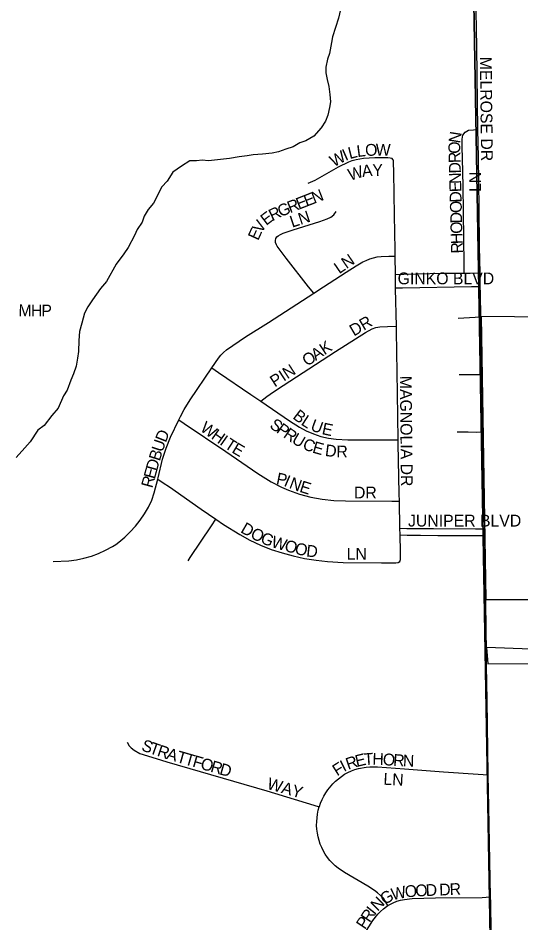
# Model space of a CAD drawing. Extents: x 1985906 to 2360102, y 891258 to 1222054.
# Drawn here: x 2128183 to 2130312, y 1037407 to 1041237 of the extents above; entities that cross this region are included whole.
import ezdxf

# ---------------------------------------------------------------- set-up
doc = ezdxf.new("R2010")
doc.units = 0
for name, color, linetype in [('GM_X_City_Street', 7, 'Continuous'), ('GM_X_City_Street_Text', 7, 'Continuous'), ('GM_X_Corporation', 7, 'Continuous'), ('GM_X_Minor_River', 7, 'Continuous'), ('GM_X_Section', 7, 'Continuous'), ('GM_X_Township_Road', 7, 'Continuous')]:
    doc.layers.add(name, color=color, linetype=linetype)

msp = doc.modelspace()

# ---------------------------------------------------------------- linework, layer by layer
at = {"layer": 'GM_X_City_Street'}
for points in [[(2130129.7, 1040765.1), (2130127.6, 1040879.5), (2130124.6, 1041114.9), (2130121.4, 1041343.2), (2130120.6, 1041445.2), (2130120.4, 1041459.6)], [(2130071.5, 1040157.7), (2130071.1, 1040195.2), (2130066.9, 1040526.3), (2130063.7, 1040643), (2130062.7, 1040692.7), (2130062.9, 1040725.3), (2130065.9, 1040741.2), (2130075, 1040754.4), (2130089.3, 1040762.6), (2130110.7, 1040763.9), (2130129.7, 1040765.1)], [(2130138.6, 1040158.3), (2130136.8, 1040269), (2130135, 1040434.1), (2130131.9, 1040648.5), (2130129.7, 1040765.1)], [(2129411.6, 1040538.5), (2129440.7, 1040550.6), (2129539.3, 1040607.9), (2129582.8, 1040629.2), (2129597.9, 1040634.8), (2129613.5, 1040639.1), (2129629.3, 1040642.1), (2129645.4, 1040644), (2129693.8, 1040647.1), (2129732.9, 1040647.1), (2129748.2, 1040646.5), (2129757.9, 1040645.9), (2129765.2, 1040643.6)], [(2129779.9, 1040229.5), (2129779.7, 1040255.8), (2129776.3, 1040403.3), (2129773.8, 1040583.6), (2129772, 1040627.3), (2129771.6, 1040633.2), (2129770.2, 1040637.7), (2129765.2, 1040643.6)], [(2129434.5, 1040072.4), (2129412.8, 1040100.3), (2129318.5, 1040221.3), (2129279.8, 1040271.1), (2129276.4, 1040277.9), (2129272.9, 1040287), (2129272, 1040296.3), (2129274.1, 1040304.8), (2129278.2, 1040311.2), (2129283.6, 1040316.1), (2129293.5, 1040321.8), (2129304.8, 1040327), (2129347.3, 1040341.4), (2129459.8, 1040376.4), (2129491.2, 1040387.8), (2129506.3, 1040394.9), (2129519.6, 1040405), (2129529.5, 1040418.5)], [(2129434.5, 1040072.4), (2129476.4, 1040099.3), (2129572.5, 1040161.3), (2129613.5, 1040188.5), (2129641.7, 1040204.9), (2129656.5, 1040211.8), (2129671.7, 1040217.8), (2129687.2, 1040222.6), (2129703.2, 1040226.2), (2129719.4, 1040228), (2129752, 1040228.8), (2129779.9, 1040229.5)], [(2129780.6, 1040152.1), (2129779.9, 1040229.5)], [(2129780.6, 1040152.1), (2129815.4, 1040152.9), (2129981.3, 1040156.8), (2130071.5, 1040157.7)], [(2129780.8, 1040095.5), (2129780.8, 1040124.6), (2129780.6, 1040152.1)], [(2130071.5, 1040157.7), (2130097.4, 1040157.9), (2130138.6, 1040158.3)], [(2130139.5, 1040101.3), (2130138.6, 1040158.3)], [(2129780.8, 1040095.5), (2129811, 1040096), (2130102.2, 1040100.7), (2130139.5, 1040101.3)], [(2129784.7, 1039932.6), (2129780.8, 1040091.8), (2129780.8, 1040095.5)], [(2130141.8, 1039972.1), (2130140, 1040071.2), (2130139.5, 1040101.3)], [(2129003.4, 1039756.8), (2129030.9, 1039797.4), (2129041, 1039810.3), (2129052.2, 1039822), (2129064.8, 1039832.3), (2129145.7, 1039887.7), (2129242.6, 1039948.9), (2129434.5, 1040072.4)], [(2130046.2, 1039967), (2130141.8, 1039972.1)], [(2129210.5, 1039615.5), (2129236.4, 1039635.2), (2129249.5, 1039645.2), (2129276.8, 1039664), (2129527.2, 1039826), (2129653.1, 1039906.5), (2129682.2, 1039921.8), (2129697.5, 1039927.5), (2129713.7, 1039930.8), (2129746.8, 1039931.6), (2129784.7, 1039932.6)], [(2129792.3, 1039452.3), (2129789.2, 1039649.4), (2129785.1, 1039911.5), (2129784.7, 1039932.6)], [(2128863.2, 1039537), (2128870.2, 1039551.3), (2128885.4, 1039580.2), (2128911.3, 1039621.8), (2129003.4, 1039756.8)], [(2129003.4, 1039756.8), (2129032.1, 1039736.7), (2129168.8, 1039644), (2129210.5, 1039615.5)], [(2130050.2, 1039728), (2130110.9, 1039728.7), (2130146.4, 1039729.1)], [(2129210.5, 1039615.5), (2129332.3, 1039532.2), (2129374, 1039505.6), (2129403, 1039489.7), (2129433.3, 1039476.9), (2129464.7, 1039466.7), (2129496.9, 1039459), (2129529.5, 1039454.5), (2129579, 1039452.3), (2129711.2, 1039451.9), (2129760.7, 1039452.1), (2129792.3, 1039452.3)], [(2128774.4, 1039285.4), (2128775.9, 1039291.1), (2128795, 1039370.7), (2128809.3, 1039417.5), (2128827.6, 1039462.9), (2128863.2, 1039537)], [(2128863.2, 1039537), (2128885.9, 1039521.7), (2129062.6, 1039402.1), (2129198.5, 1039309.8), (2129254.3, 1039275), (2129297.9, 1039252.1), (2129328, 1039238.9), (2129374.4, 1039222.4), (2129422.1, 1039209.6), (2129470.6, 1039200.6), (2129519.6, 1039195.5), (2129568.9, 1039193.3), (2129765.5, 1039192.8), (2129796.9, 1039192.8)], [(2130041.3, 1039486), (2130087.8, 1039485.9), (2130122.6, 1039485.1), (2130150.8, 1039485.9)], [(2129796.9, 1039192.8), (2129796.2, 1039223.3), (2129792.5, 1039436.4), (2129792.3, 1039452.3)], [(2128331.9, 1038937.6), (2128397.2, 1038940.6), (2128429.7, 1038944.2), (2128461.8, 1038950.6), (2128493.2, 1038959.4), (2128524, 1038970.5), (2128553.6, 1038984.4), (2128582.2, 1039000.3), (2128596.1, 1039009), (2128609.4, 1039018.5), (2128634.3, 1039039.6), (2128657.8, 1039062.3), (2128679.8, 1039086.3), (2128700.2, 1039111.8), (2128718.6, 1039138.9), (2128734.7, 1039167.3), (2128748.5, 1039197), (2128759.3, 1039227.8), (2128774.4, 1039285.4)], [(2128774.4, 1039285.4), (2128796.6, 1039270.7), (2128823.9, 1039252.8), (2128957.8, 1039159.2), (2129020.3, 1039116.1)], [(2129799.6, 1039077.5), (2129796.9, 1039192.8)], [(2128902.4, 1038939.9), (2128911, 1038953.6), (2129001.6, 1039088.3), (2129020.3, 1039116.1)], [(2129020.3, 1039116.1), (2129052, 1039094.3), (2129121.3, 1039051.1), (2129164.3, 1039027.4), (2129208.7, 1039006.7), (2129254.3, 1038988.6), (2129300.8, 1038973.2), (2129348.1, 1038960.5), (2129396.1, 1038950.3), (2129444.6, 1038942.5), (2129493.3, 1038937), (2129558.5, 1038932.9), (2129721.6, 1038931.5), (2129781.5, 1038932.1), (2129791.8, 1038933.3), (2129798.6, 1038937)], [(2129799.6, 1039077.5), (2129828.8, 1039077.4), (2129941.6, 1039077.3), (2130118.8, 1039075.4), (2130158.2, 1039075)], [(2129800.3, 1039049.4), (2129799.6, 1039077.5)], [(2129798.6, 1038937), (2129801.8, 1038945), (2129802.2, 1038954.7), (2129801.9, 1038977.4), (2129800.3, 1039049.4)], [(2129800.3, 1039049.4), (2129830.5, 1039049.1), (2129887, 1039048.4), (2129959.5, 1039047.5), (2130061.7, 1039047.5), (2130124.6, 1039047.5), (2130158.7, 1039047.6)], [(2130165.8, 1038556.3), (2130163.9, 1038652.3), (2130162.4, 1038766.8)], [(2130173.3, 1038034.8), (2130168.5, 1038350.2), (2130166.1, 1038496.9)], [(2128644.8, 1038171.9), (2128652.6, 1038157.5), (2128662, 1038147.8), (2128674.8, 1038138.4), (2128699.1, 1038123.8), (2128767.2, 1038103.3), (2128812.8, 1038089.7), (2129236, 1037966.7), (2129435.2, 1037906.1), (2129458.2, 1037899.1)], [(2129458.2, 1037899.1), (2129458.3, 1037899.5), (2129463.7, 1037914.7), (2129470.1, 1037929.5), (2129477.5, 1037943.8), (2129485.8, 1037957.7), (2129494.9, 1037971), (2129515.5, 1037995.8), (2129526.9, 1038007.1), (2129539.2, 1038017.5), (2129565.3, 1038036.4), (2129579.3, 1038044.2), (2129594, 1038050.7), (2129609.1, 1038056.2), (2129624.6, 1038060.7), (2129656.3, 1038066.5), (2129672.4, 1038068), (2129704.8, 1038068.3), (2129819.3, 1038060), (2129983.4, 1038047.2), (2130131.2, 1038037.6), (2130173.3, 1038034.8)], [(2130183.1, 1037517.2), (2130175.4, 1037896.8), (2130173.3, 1038034.8)], [(2129748.3, 1037480.5), (2129743.6, 1037488.8), (2129735.8, 1037502.5), (2129729.2, 1037511.5), (2129717.6, 1037523.6), (2129704.7, 1037534.5), (2129691.3, 1037544.4), (2129663.6, 1037562.5), (2129564.1, 1037620.5), (2129537.4, 1037638.8), (2129524.9, 1037649), (2129513.3, 1037660), (2129502.4, 1037671.7), (2129492.5, 1037684.4), (2129483.6, 1037697.8), (2129475.6, 1037711.8), (2129468.5, 1037726.3), (2129462.4, 1037741.3), (2129457.2, 1037756.6), (2129453, 1037772.2), (2129449.9, 1037788), (2129447.8, 1037803.9), (2129446.9, 1037820), (2129447.1, 1037836.1), (2129450.7, 1037868.2), (2129454, 1037884), (2129458.2, 1037899.1)], [(2129748.3, 1037480.5), (2129756.4, 1037485.6), (2129771.2, 1037492.9), (2129786.5, 1037498.8), (2129802.3, 1037503.5), (2129818.4, 1037506.9), (2129851.2, 1037510.4), (2129950, 1037513.2), (2130147.7, 1037515.1), (2130164.1, 1037516.1), (2130183.1, 1037517.2)], [(2130188.5, 1037189.7), (2130186, 1037367.3), (2130183.6, 1037495.1), (2130183.1, 1037517.2)], [(2129640.6, 1037349), (2129685.3, 1037418.3), (2129705.5, 1037444.3), (2129716.8, 1037456.2), (2129729.2, 1037467.2), (2129742.4, 1037477), (2129748.3, 1037480.5)]]:
    msp.add_lwpolyline(points, dxfattribs=at)
at = {"layer": 'GM_X_Corporation'}
for points in [[(2132676.9, 1039948.2), (2130143.9, 1039974.3), (2130163.3, 1038776.5), (2130355.5, 1038775.6)], [(2130355.4, 1038565.5), (2130166.1, 1038573.4), (2130171.7, 1038503.9), (2130355.4, 1038505.5)]]:
    msp.add_lwpolyline(points, dxfattribs=at)
at = {"layer": 'GM_X_Minor_River'}
for points in [[(2129548.4, 1041272.8), (2129538.8, 1041236.6), (2129513.7, 1041158), (2129510, 1041133.9), (2129500.6, 1041087.7), (2129492.9, 1041063.5), (2129485.3, 1041029.3), (2129485.6, 1041005.2), (2129492, 1040977.2), (2129498.4, 1040947.2), (2129502.9, 1040913.2), (2129505.3, 1040883.1), (2129501.6, 1040859), (2129493.9, 1040826.8), (2129484.2, 1040800.6), (2129466.5, 1040772.3), (2129434.9, 1040737.8), (2129401, 1040717.3), (2129375, 1040708.9), (2129347.1, 1040692.5), (2129317.1, 1040682.1), (2129285.1, 1040671.6), (2129259.1, 1040665.2), (2129217, 1040660.7), (2129178.8, 1040658.2), (2129152.8, 1040653.8), (2129118.7, 1040649.3), (2129078.6, 1040642.8), (2129040.5, 1040638.3), (2128988.4, 1040633.6), (2128962.3, 1040635.2), (2128938.2, 1040632.9), (2128910.1, 1040632.5), (2128874.2, 1040610), (2128838.4, 1040585.4)], [(2128838.4, 1040585.4), (2128814.8, 1040547), (2128791, 1040522.6), (2128755.7, 1040453.9), (2128734, 1040427.6), (2128716.3, 1040399.3), (2128708.6, 1040373.1), (2128686.9, 1040342.7), (2128675.2, 1040316.5), (2128649.7, 1040266), (2128630, 1040239.7), (2128598.4, 1040195.1), (2128557.2, 1040122.3), (2128531.5, 1040091.9), (2128498, 1040045.3), (2128478.3, 1040015), (2128464.6, 1039988.8), (2128453.1, 1039946.5), (2128443.5, 1039910.2), (2128440, 1039872.1), (2128438.6, 1039825.9), (2128434.9, 1039797.8), (2128429.3, 1039763.6), (2128417.7, 1039731.4), (2128406, 1039705.1), (2128390.5, 1039662.8), (2128374.7, 1039638.5), (2128353.3, 1039586.1), (2128325.6, 1039555.7), (2128294, 1039513.1), (2128266.2, 1039492.7), (2128234.7, 1039444.1), (2128210.9, 1039417.7), (2128175.3, 1039377.1)]]:
    msp.add_lwpolyline(points, dxfattribs=at)
at = {"layer": 'GM_X_Section'}
for points in [[(2130109.5, 1041463.5), (2135234.2, 1041549.5), (2135365.6, 1036205), (2130202.8, 1036134.8)], [(2124934, 1041489.3), (2130109.5, 1041463.5), (2130202.8, 1036134.8), (2125019.2, 1036172.5)]]:
    msp.add_lwpolyline(points, close=True, dxfattribs=at)
at = {"layer": 'GM_X_Township_Road'}
for points in [[(2130146.4, 1039729.1), (2130141.8, 1039972.1)], [(2130150.8, 1039485.9), (2130147, 1039701.9), (2130146.4, 1039729.1)], [(2130158.2, 1039075), (2130154.8, 1039242.3), (2130150.8, 1039485.9)], [(2130158.7, 1039047.6), (2130158.2, 1039075)], [(2130162.4, 1038766.8), (2130162.3, 1038870.2), (2130158.7, 1039047.6)], [(2130166.1, 1038496.9), (2130165.8, 1038556.3)]]:
    msp.add_lwpolyline(points, dxfattribs=at)

# ---------------------------------------------------------------- texts
at = {"layer": 'GM_X_City_Street_Text'}
for s, rotation, p in [('MELROSE DR', 270.6516, (2130137.9, 1041073.1)), ('N', 81.0012, (2130054, 1040705.1)), ('L', 14.3543, (2129586.9, 1040640.1)), ('L', 7.3961, (2129619.5, 1040648.5)), ('O', 3.3896, (2129653.5, 1040652.9)), ('W', 358.8062, (2129696.3, 1040655.5)), ('O', 91.4805, (2130055.3, 1040663.6)), ('W', 28.2347, (2129519.4, 1040605.3)), ('I', 23.9048, (2129568.9, 1040631.9)), ('R', 91.4782, (2130056.4, 1040624)), ('W', 16.3772, (2129588.2, 1040548.5)), ('A', 5.9781, (2129640.7, 1040564.2)), ('Y', 1.4425, (2129683.4, 1040568.7)), ('D', 91.4805, (2130057.5, 1040580)), ('N', 91.4862, (2130058.6, 1040536)), ('LN', 90, (2130142.6, 1040501.3)), ('E', 91.5009, (2130059.6, 1040500.9)), ('E', 21.3905, (2129403.7, 1040438.3)), ('N', 21.4225, (2129436.6, 1040451.2)), ('D', 91.4911, (2130060.7, 1040456.8)), ('R', 21.409, (2129334.1, 1040411)), ('E', 21.4069, (2129371, 1040425.5)), ('O', 91.4862, (2130061.9, 1040412.8)), ('E', 37.3288, (2129233.1, 1040357.1)), ('R', 25.6638, (2129258.8, 1040377)), ('G', 23.0149, (2129294, 1040393.9)), ('LN', 18.4386, (2129343.1, 1040349.6)), ('V', 57.8556, (2129212.9, 1040323.3)), ('D', 91.4911, (2130063, 1040368.9)), ('E', 65.5244, (2129199.1, 1040292.8)), ('O', 91.4862, (2130064.1, 1040324.9)), ('H', 91.4911, (2130065.3, 1040280.9)), ('R', 91.4813, (2130066.3, 1040241.3)), ('LN', 34.505, (2129542.4, 1040152.6)), ('GINKO BLVD', 0, (2129789.7, 1040110.3)), ('M', 359.5629, (2128184.7, 1039975)), ('H', 359.5762, (2128237.5, 1039974.6)), ('P', 359.5628, (2128281.5, 1039974.3)), ('DR', 30.4667, (2129604.4, 1039888.9)), ('K', 33.2802, (2129479.7, 1039809.5)), ('O', 33.296, (2129406.2, 1039761.2)), ('A', 33.2657, (2129443, 1039785.3)), ('PIN', 33.0243, (2129269.8, 1039673.2)), ('MAGNOLIA DR', 270.5779, (2129799.1, 1039722.7)), ('B', 322.3529, (2129342.3, 1039545.1)), ('S', 325.3325, (2129244.2, 1039505.7)), ('L', 327.2559, (2129377.4, 1039518.2)), ('U', 339.6777, (2129417.4, 1039494)), ('W', 324.9157, (2128950.3, 1039492.6)), ('P', 325.3806, (2129273.2, 1039485.6)), ('R', 325.8951, (2129302.6, 1039465.3)), ('E', 348.143, (2129466.3, 1039476.5)), ('D', 68.2392, (2128808, 1039438)), ('H', 324.9095, (2128997.1, 1039459.7)), ('I', 324.9165, (2129033.1, 1039434.4)), ('T', 327.0581, (2129052.8, 1039420.6)), ('U', 329.018, (2129337.9, 1039441.5)), ('U', 71.4959, (2128794.3, 1039397)), ('E', 329.5466, (2129084.3, 1039400.3)), ('C', 338.5679, (2129383.8, 1039414.9)), ('E', 344.3076, (2129425.8, 1039398.7)), ('D', 352.8025, (2129480.4, 1039384.1)), ('R', 359.008, (2129530, 1039378.2)), ('B', 72.7401, (2128782.6, 1039359.5)), ('D', 74.4689, (2128771, 1039317.4)), ('E', 74.5388, (2128761.6, 1039283.5)), ('P', 348.5025, (2129272.9, 1039265.1)), ('R', 74.5383, (2128751, 1039245.4)), ('I', 336.6809, (2129304.8, 1039258.9)), ('N', 339.3683, (2129327.3, 1039249.3)), ('E', 342.5516, (2129371.3, 1039232.8)), ('DR', 0, (2129604.9, 1039203.9)), ('JUNIPER BLVD', 0, (2129833.7, 1039085.1)), ('D', 329.9732, (2129121.5, 1039062.6)), ('O', 333.7272, (2129162.8, 1039038.9)), ('G', 337.32, (2129205.3, 1039018)), ('W', 343.5479, (2129251.5, 1038999.1)), ('O', 344.9458, (2129307.6, 1038982.5)), ('O', 345.9618, (2129351.1, 1038970.8)), ('D', 353.9214, (2129401.2, 1038958.8)), ('LN', 0, (2129574.1, 1038944.3)), ('S', 340.9343, (2128701.6, 1038138.6)), ('T', 340.9437, (2128734.9, 1038127.1)), ('R', 341.1322, (2128768.3, 1038115.5)), ('A', 343.111, (2128807.6, 1038102.2)), ('T', 344.0541, (2128850.5, 1038089.1)), ('T', 344.0541, (2128884.4, 1038079.4)), ('E', 13.5659, (2129616.3, 1038067.1)), ('T', 3.9922, (2129648.4, 1038075)), ('H', 357.8142, (2129682, 1038077.5)), ('O', 355.9097, (2129725.6, 1038075.8)), ('R', 355.9161, (2129769.5, 1038072.7)), ('F', 344.0541, (2128918.2, 1038069.8)), ('O', 344.053, (2128952, 1038060.1)), ('R', 344.0535, (2128994.3, 1038048)), ('D', 344.053, (2129032.4, 1038037.1)), ('F', 32.2197, (2129533.4, 1038027.3)), ('I', 27.2494, (2129562.2, 1038045.5)), ('R', 18.5886, (2129579.9, 1038054.8)), ('N', 358.6753, (2129811.6, 1038069.7)), ('WAY', 343.8118, (2129233.5, 1037975.9)), ('LN', 356.989, (2129728.5, 1037992.5)), ('W', 11.8869, (2129767.9, 1037503.2)), ('O', 5.3844, (2129822.4, 1037514.8)), ('O', 2.7107, (2129865.6, 1037518.9)), ('D', 2.1858, (2129909.4, 1037520.9)), ('D', 2.1858, (2129966.6, 1037523.1)), ('R', 2.2141, (2130010.6, 1037524.8)), ('N', 44.3972, (2129704.8, 1037454)), ('G', 29.9292, (2129733.6, 1037482.7)), ('I', 51.8452, (2129692.4, 1037437.9)), ('P', 56.416, (2129651.6, 1037376.5)), ('R', 56.4417, (2129671.1, 1037405.8))]:
    msp.add_text(s, height=50, rotation=rotation, dxfattribs=at).set_placement(p)

doc.saveas('drawing.dxf')
